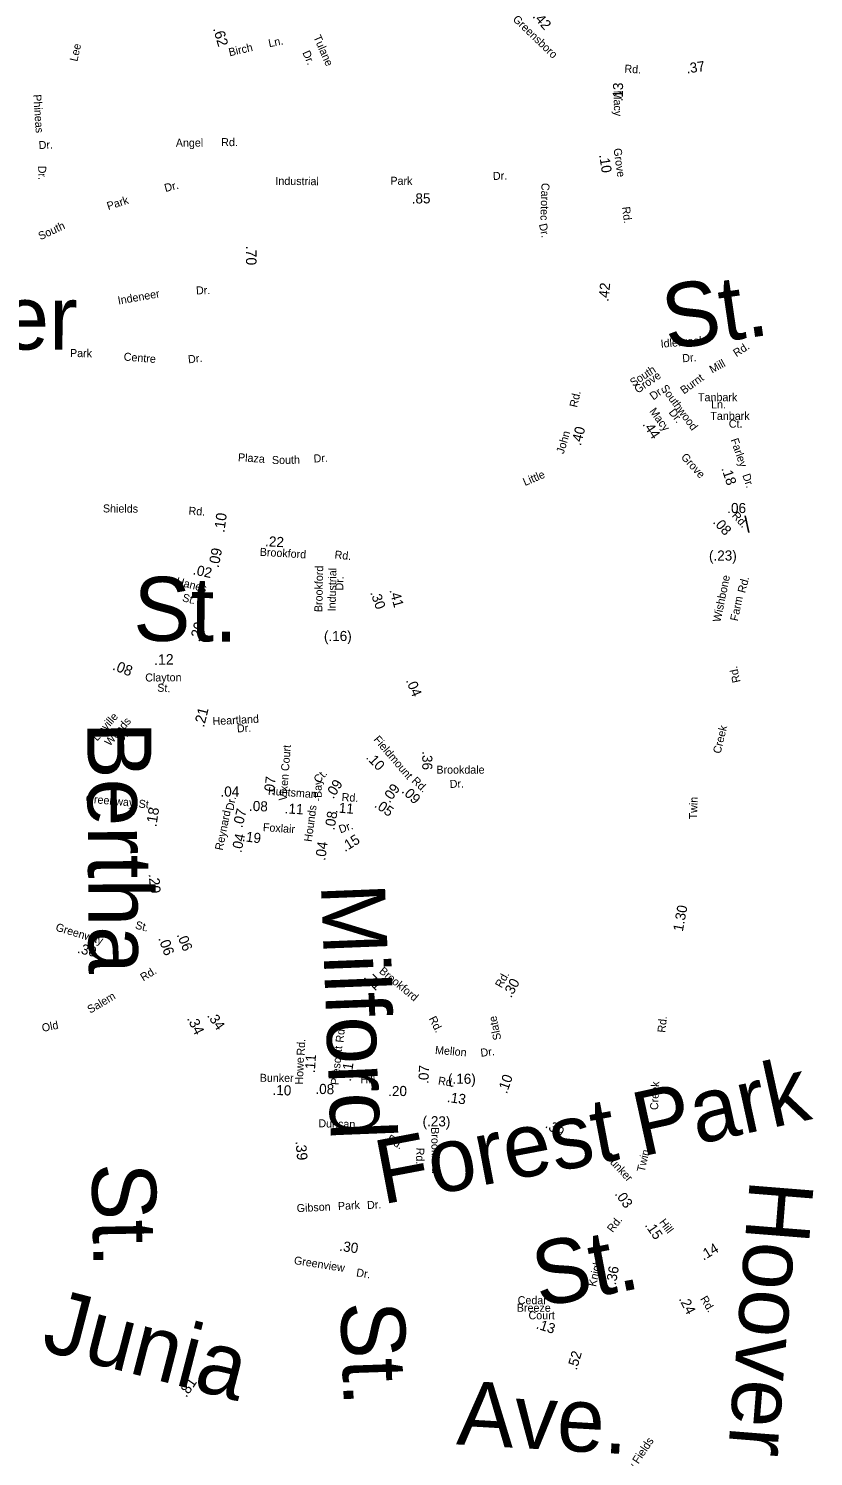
# Model space of a CAD drawing. Extents: x 1553981 to 1780076, y 812965 to 996873.
# Drawn here: x 1639957 to 1641122, y 846574 to 848692 of the extents above; entities that cross this region are included whole.
import ezdxf

# ---------------------------------------------------------------- set-up
doc = ezdxf.new("R2010")
doc.units = 0
for name, color, linetype in [('Exist Road Non-System Type 51 Label', 7, 'Continuous'), ('Exist Road Primary NC Service Mileage Hundredths English Label', 7, 'Continuous'), ('Exist Road Secondary Mileage Hundredths English Label', 7, 'Continuous'), ('Map Preparation Border Antique Large Shape', 7, 'Continuous')]:
    doc.layers.add(name, color=color, linetype=linetype)

msp = doc.modelspace()

# ---------------------------------------------------------------- linework, layer by layer
at = {"layer": 'Exist Road Secondary Mileage Hundredths English Label'}
msp.add_lwpolyline([(1641020.6, 847969.6), (1641025.8, 847944.9)], dxfattribs=at)

# ---------------------------------------------------------------- texts
at = {"layer": 'Exist Road Non-System Type 51 Label'}
for s, height, rotation, p in [('Tulane', 11.88, 293.672, (1640379.7, 848679.8)), ('Lee', 11.88, 77.356, (1640029.8, 848642.8)), ('Birch', 11.87, 13.0506, (1640255.8, 848651.1)), ('Ln.', 11.88, 11.3789, (1640314.5, 848664.6)), ('Dr.', 11.88, 293.672, (1640363.4, 848656.7)), ('Phineas', 11.87, 273.8641, (1639964.4, 848594.3)), ('Rd.', 11.88, 0.061, (1640243.3, 848517.9)), ('Dr.', 11.88, 2.261, (1639972.7, 848513.5)), ('Angel', 11.87, 0.4495, (1640176, 848516.9)), ('Dr.', 11.88, 271.0257, (1639971.7, 848488.8)), ('Dr.', 11.88, 14.2291, (1640160.6, 848449.8)), ('Carotec', 11.88, 268.1736, (1640718.5, 848463.5)), ('Park', 11.88, 17.8886, (1640075.8, 848422.9)), ('South', 11.88, 25.055, (1639975.2, 848378.3)), ('Dr.', 11.88, 281.5531, (1640714.6, 848402)), ('St.', 95, 8.2818, (1640905, 848215.9)), ('Tower', 95, 359.6405, (1639677.1, 848217.9)), ('Indeneer', 11.88, 9.9315, (1640090.9, 848282.9)), ('Dr.', 11.87, 1.3513, (1640206, 848297.9)), ('Idlebrook', 11.88, 4.8541, (1640895.7, 848218.8)), ('Park', 11.87, 359.2742, (1640018.9, 848205.1)), ('Rd.', 11.88, 32.7758, (1641007.5, 848204.6)), ('Centre', 11.88, 355.5663, (1640098.3, 848199.9)), ('Dr.', 11.88, 6.572, (1640194.7, 848195.6)), ('Dr.', 11.88, 4.8541, (1640927.7, 848197.2)), ('Mill', 11.88, 28.9931, (1640971.6, 848180.4)), ('South', 11.88, 32.8081, (1640854.4, 848160.8)), ('Grove', 11.88, 34.4157, (1640861.2, 848150.5)), ('Burnt', 11.88, 36.036, (1640929.7, 848149.3)), ('Dr.', 11.88, 36.1491, (1640884.3, 848140.5)), ('Southwood', 11.87, 306.4798, (1640894.6, 848158.7)), ('Dr.', 11.88, 308.0058, (1640906.5, 848122.7)), ('Plaza', 11.88, 356.1729, (1640267.9, 848050.6)), ('South', 11.88, 0.7907, (1640318.6, 848046.2)), ('Dr.', 11.88, 3.7488, (1640380.7, 848048.4)), ('St.', 95, 359.4163, (1640112.6, 847784.3)), ('Hanes', 11.88, 345.6258, (1640175.6, 847867.1)), ('St.', 11.87, 345.0831, (1640184.7, 847843)), ('Linville', 11.88, 49.0111, (1640059.3, 847634.4)), ('Woods', 11.88, 49.0111, (1640078, 847626.9)), ('Heartland', 11.88, 3.0149, (1640230.7, 847658.8)), ('Bertha', 95, 270.36, (1640044.5, 847664.1)), ('Dr.', 11.88, 47.318, (1640095.5, 847632)), ('Dr.', 11.88, 3.0149, (1640266.9, 847648)), ('Brookdale', 11.87, 0.0008, (1640562.5, 847586.9)), ('Dr.', 11.88, 1.7378, (1640582.4, 847565.7)), ('Greenway', 11.87, 354.9856, (1640041.8, 847544.2)), ('St.', 11.88, 355.2905, (1640120.4, 847536.6)), ('Milford', 95, 272.2763, (1640391.1, 847422.6)), ('Park', 95, 12.3877, (1640866.5, 847018.6)), ('Forest', 95, 10.776, (1640482.3, 846947.6)), ('Duncan', 11.88, 358.4873, (1640387.3, 847062.3)), ('Rd.', 11.88, 327.9058, (1640487.9, 847042.2)), ('St.', 95, 271.0625, (1640051.1, 847008.8)), ('Hoover', 95, 265.4332, (1641027.7, 846986.4)), ('Gibson', 11.87, 2.9542, (1640355.6, 846936.2)), ('Park', 11.87, 2.9542, (1640416.7, 846939.4)), ('Dr.', 11.87, 2.9542, (1640459.9, 846940.9)), ('St.', 95, 10.776, (1640715.2, 846795)), ('Junia', 95, 345.4682, (1639974.1, 846732.1)), ('St.', 95, 271.9679, (1640420, 846802.6)), ('Ave.', 95, 356.6884, (1640591.3, 846591.8))]:
    msp.add_text(s, height=height, rotation=rotation, dxfattribs=at).set_placement(p)
for s, p in [('Tanbark', (1640950.6, 848139.5)), ('Ln.', (1640970, 848128.8)), ('Tanbark', (1640968.9, 848111.8)), ('Ct.', (1640996.3, 848100.2))]:
    msp.add_text(s, height=11.88, dxfattribs=at).set_placement(p)
at = {"layer": 'Exist Road Primary NC Service Mileage Hundredths English Label'}
for s, rotation, p in [('.62', 286.3131, (1640231, 848692.2)), ('.70', 270, (1640280.1, 848370.3)), ('.10', 82.2395, (1640247.9, 847944)), ('.09', 79.0972, (1640239.4, 847891.6)), ('.20', 74.924, (1640211.4, 847781.4)), ('.21', 75.9423, (1640217.7, 847654.8)), ('.18', 81.2538, (1640147, 847507.1)), ('.20', 274.7278, (1640135.7, 847437.7)), ('.06', 290.4579, (1640149.6, 847342.6)), ('.34', 296.2807, (1640192.1, 847223.7)), ('.39', 275.4373, (1640353.4, 847041.4)), ('.81', 55.4653, (1640191.5, 846660.4))]:
    msp.add_text(s, height=15.62, rotation=rotation, dxfattribs=at).set_placement(p)
at = {"layer": 'Exist Road Secondary Mileage Hundredths English Label'}
for s, height, rotation, p in [('.42', 15, 311.6396, (1640704.5, 848710)), ('.37', 15, 8.2052, (1640934.1, 848625.6)), ('.13', 15, 88.8386, (1640839, 848584.2)), ('.10', 15, 278.6954, (1640803.9, 848504.9)), ('.85', 15, 0.4943, (1640525.9, 848432.8)), ('.42', 15, 84.0837, (1640817.6, 848286.8)), ('.40', 15, 75.5411, (1640776.6, 848072.6)), ('.44', 15, 303.8661, (1640867.7, 848105.1)), ('.18', 15, 288.6089, (1640985.1, 848039.7)), ('.08', 15, 312.1371, (1640971.9, 847959.6)), ('.22', 15, 356.7434, (1640308.1, 847924.4)), ('(.23)', 15, 0.2794, (1640966.9, 847902.9)), ('.02', 15, 347.985, (1640200.5, 847882.8)), ('.30', 15, 289.9324, (1640464.1, 847855.5)), ('.41', 15, 285.3415, (1640492.7, 847859)), ('(.16)', 15, 0.2851, (1640395.7, 847783.5)), ('.08', 15.62, 338.3937, (1640081, 847741.6)), ('.12', 15.62, 0.9142, (1640143.8, 847748.3)), ('.04', 15, 292.6894, (1640516.9, 847725.2)), ('.10', 15, 313.8535, (1640457.2, 847610.2)), ('.36', 15, 269.7762, (1640541.6, 847620.2)), ('.07', 15, 82.9158, (1640321.1, 847554.1)), ('.09', 15, 58.1945, (1640409.5, 847548.5)), ('.04', 15, 0.0772, (1640242.2, 847552.9)), ('.09', 15, 54.2242, (1640493.1, 847542.4)), ('.09', 15, 316.306, (1640510, 847559.8)), ('.07', 15, 76.2348, (1640274.6, 847505.7)), ('.08', 15, 357.7608, (1640284.3, 847531.8)), ('.11', 15, 356.7139, (1640337.2, 847528)), ('.11', 15, 355.3422, (1640411.7, 847529.5)), ('.05', 15, 325.0689, (1640469.5, 847538.2)), ('.08', 15, 80.3801, (1640411.2, 847502.4)), ('.04', 15, 77.8836, (1640273.1, 847468.9)), ('.19', 15, 352.5448, (1640273.7, 847487)), ('.15', 15, 31.8918, (1640426.9, 847470.4)), ('.04', 15, 82.051, (1640397.5, 847457.4)), ('1.30', 15, 79.4554, (1640928, 847351.9)), ('.06', 15, 292.1577, (1640177, 847347.8)), ('.30', 15, 346.2839, (1640028.9, 847321.3)), ('.71', 15, 315.5045, (1640453.5, 847284)), ('.30', 15, 61.3609, (1640673.4, 847253.3)), ('.34', 15, 304.561, (1640221.7, 847227.7)), ('.11', 15, 86.0698, (1640382.1, 847142.3)), ('.11', 15, 81.8594, (1640435.6, 847129.7)), ('.07', 15, 87.851, (1640550.7, 847126.4)), ('(.16)', 15, 0.0214, (1640579.7, 847126.7)), ('.10', 15, 70.76, (1640666.9, 847111.1)), ('.10', 15, 358.0364, (1640319.2, 847110.3)), ('.08', 15, 358.8321, (1640382.9, 847111.8)), ('.20', 15, 0.244, (1640491, 847108.5)), ('.13', 15, 352.0314, (1640577.6, 847099.9)), ('(.23)', 15, 359.0288, (1640541.9, 847064)), ('.39', 15, 323.7311, (1640722.9, 847063)), ('.03', 15, 305.9896, (1640826.5, 846963.2)), ('.15', 15, 304.7994, (1640871.1, 846916.9)), ('.30', 15, 351.9021, (1640417.9, 846879.1)), ('.14', 15, 30.8344, (1640958.7, 846864.2)), ('.36', 15, 80.0991, (1640828.6, 846827.5)), ('.24', 15, 297.7015, (1640921.8, 846807.6)), ('.13', 15, 342.0619, (1640709.4, 846764.1)), ('.52', 15, 73.6324, (1640770.6, 846701.1))]:
    msp.add_text(s, height=height, rotation=rotation, dxfattribs=at).set_placement(p)
msp.add_text('.06', height=15, dxfattribs=at).set_placement((1640994, 847973.5))
at = {"layer": 'Map Preparation Border Antique Large Shape'}
for s, height, rotation, p in [('Greensboro', 11.87, 316.2144, (1640674.9, 848705)), ('Rd.', 11.88, 356.4838, (1640841.2, 848627.1)), ('Macy', 11.87, 270.977, (1640825.4, 848600.2)), ('Grove', 11.87, 277.742, (1640825.3, 848514.1)), ('Industrial', 11.88, 359.4896, (1640323.6, 848460.5)), ('Park', 11.88, 359.4896, (1640494.2, 848460.7)), ('Dr.', 11.88, 1.7111, (1640646.5, 848467.7)), ('Rd.', 11.88, 276.9588, (1640837.9, 848427.5)), ('Rd.', 11.88, 76.8694, (1640771.2, 848129.5)), ('Macy', 11.88, 306.2601, (1640877.9, 848124.4)), ('John', 11.88, 73.1642, (1640751.3, 848060.5)), ('Farley', 11.87, 288.8848, (1640998.8, 848082.3)), ('Grove', 11.87, 312.3569, (1640924.5, 848055.9)), ('Little', 11.88, 23.0211, (1640693.9, 848013.5)), ('Dr.', 11.87, 288.6089, (1641016.2, 848029.8)), ('Shields', 11.87, 359.5535, (1640067.8, 847974.5)), ('Rd.', 11.88, 356.7835, (1640194.6, 847971.1)), ('Rd.', 11.88, 312.1371, (1641000.2, 847969.1)), ('Brookford', 11.88, 356.6257, (1640300.2, 847910.2)), ('Rd.', 11.88, 353.8971, (1640411, 847906.3)), ('Brookford', 11.88, 88.834, (1640393.2, 847826.5)), ('Industrial', 11.88, 88.834, (1640413, 847827.6)), ('Dr.', 11.88, 88.834, (1640424.4, 847858.6)), ('Wishbone', 11.88, 78.3495, (1640983.9, 847811)), ('Rd.', 11.87, 75.2022, (1641020.4, 847854.1)), ('Farm', 11.88, 78.3579, (1641009.6, 847812.6)), ('Clayton', 11.87, 0.3589, (1640130.6, 847723.6)), ('Rd.', 11.88, 102.3184, (1641013.7, 847723.1)), ('St.', 11.87, 357.3653, (1640148.2, 847708.6)), ('Fieldmount', 11.88, 310.5429, (1640468.5, 847637.1)), ('Creek', 11.87, 76.3601, (1640984, 847615.8)), ('Vixen Court', 11.875, 85.7662, (1640340.5, 847546.4)), ('-Bay', 11.88, 90, (1640392.4, 847545.5)), ('Ct.', 11.88, 46.9859, (1640387.7, 847571.6)), ('Rd.', 11.88, 316.4954, (1640525, 847575.1)), ('Huntsman', 11.88, 355.9417, (1640312.4, 847555.6)), ('Rd.', 11.88, 356.7139, (1640421.7, 847546.4)), ('Dr.', 11.88, 78.384, (1640261.2, 847531.4)), ('Hounds', 11.88, 82.1912, (1640377.5, 847485.2)), ('Twin', 11.88, 87.9012, (1640949, 847518.8)), ('Reynard', 11.88, 78.384, (1640245.3, 847472.4)), ('Foxlair', 11.88, 356.2245, (1640304.8, 847501.7)), ('Dr.', 11.88, 19.281, (1640420.1, 847498.2)), ('St.', 11.88, 345.6055, (1640114.9, 847357.2)), ('Greenway', 11.88, 343.0321, (1639996.7, 847354.2)), ('Rd.', 11.88, 31.3779, (1640127.7, 847278.5)), ('Brookford', 11.88, 320.3118, (1640476.6, 847292.3)), ('Rd.', 11.87, 60.7076, (1640659.2, 847268)), ('Salem', 11.88, 30.5464, (1640049, 847230.7)), ('Old', 11.88, 11.431, (1639978.4, 847203.7)), ('Rd.', 11.88, 297.2049, (1640550.9, 847223.4)), ('Slate', 11.88, 101.8638, (1640658.9, 847192.8)), ('Rd.', 11.88, 84.3933, (1640902.1, 847202.2)), ('Rd.', 11.88, 84.6973, (1640424.7, 847187.4)), ('Rd.', 11.87, 87.1786, (1640366.9, 847168.3)), ('Prescott', 11.88, 84.5873, (1640417.4, 847124.4)), ('Mellon', 11.88, 355.4066, (1640560.2, 847171.2)), ('Dr.', 11.88, 6.6622, (1640628.6, 847166.8)), ('Howe', 11.88, 87.7568, (1640364.5, 847125.4)), ('Bunker', 11.88, 359.7014, (1640300.4, 847129.7)), ('Hill', 11.88, 0.953, (1640449.8, 847127.4)), ('Rd.', 11.88, 350.8821, (1640564.4, 847125.9)), ('Creek', 11.87, 87.5165, (1640891.3, 847087.6)), ('Brookford', 11.88, 271.1978, (1640554.6, 847062.2)), ('Rd.', 11.88, 268.6591, (1640532.8, 847032.1)), ('Twin', 11.88, 76.954, (1640871.2, 846995.1)), ('Bunker', 11.88, 313.0161, (1640812.1, 847017.2)), ('Rd.', 11.88, 51.9538, (1640823.9, 846905.3)), ('Hill', 11.88, 306.9599, (1640892.4, 846921.1)), ('Greenview', 11.88, 351.0082, (1640350.6, 846859.4)), ('Knight', 11.88, 77.5453, (1640799.3, 846825)), ('Dr.', 11.88, 351.317, (1640443, 846841.2)), ('Rd.', 11.88, 301.5357, (1640953.4, 846807.6)), ('Meadow Fields', 11.875, 56.287, (1640826.3, 846508.4))]:
    msp.add_text(s, height=height, rotation=rotation, dxfattribs=at).set_placement(p)
for s, p in [('Breeze', (1640681.8, 846788.5)), ('Cedar', (1640683.1, 846799.7)), ('Court', (1640699.2, 846777.3))]:
    msp.add_text(s, height=11.88, dxfattribs=at).set_placement(p)

doc.saveas('drawing.dxf')
